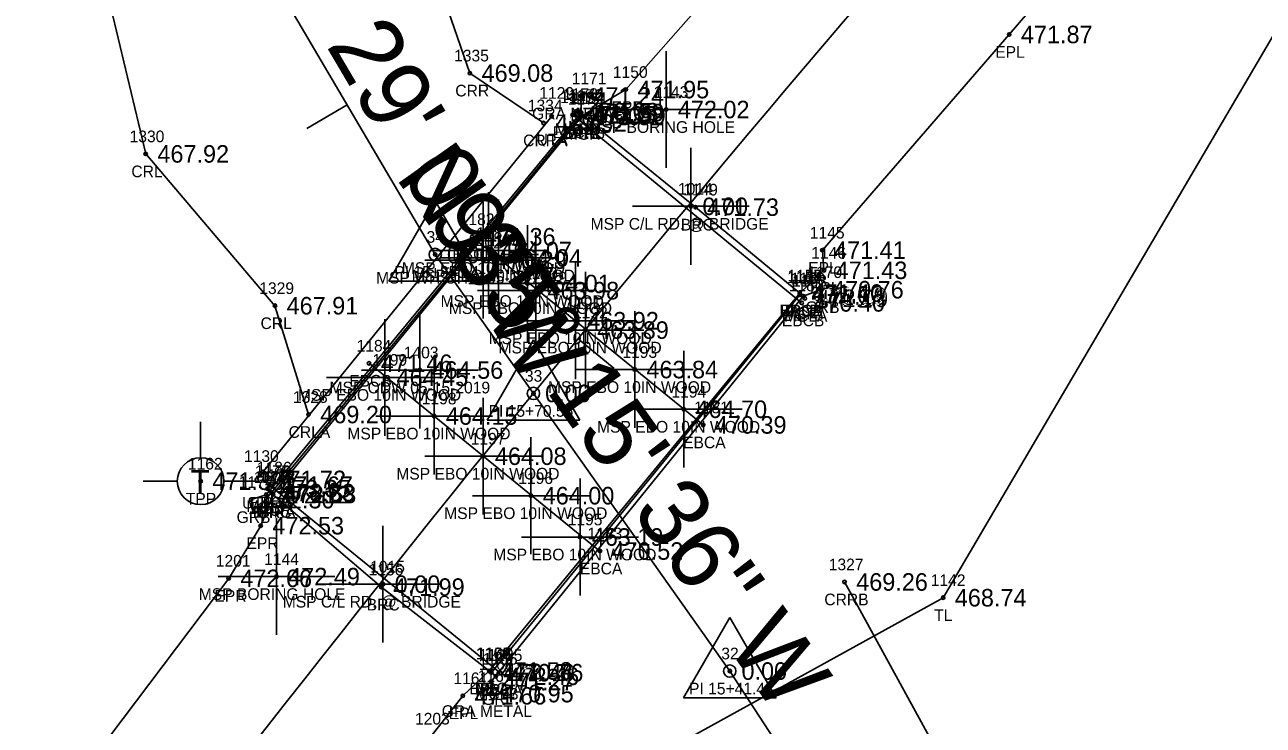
# Model space of a CAD drawing. Extents: x 1740701 to 1743138, y 748181 to 751839.
# Drawn here: x 1741552.9 to 1741658.9, y 750033.3 to 750093.3 of the extents above; entities that cross this region are included whole.
import ezdxf

# ---------------------------------------------------------------- set-up
doc = ezdxf.new("R2010")
doc.units = 0
for name, color, linetype in [('RD_EX_Bridge', 7, 'Continuous'), ('RD_EX_Bridge_txCode', 7, 'Continuous'), ('RD_EX_Conc', 7, 'Continuous'), ('RD_EX_Conc_txCode', 7, 'Continuous'), ('RD_EX_GuardRail', 7, 'Continuous'), ('RD_EX_GuardRail_txCode', 7, 'Continuous'), ('RD_EX_H2O', 7, 'Continuous'), ('RD_EX_H2O_txCode', 7, 'Continuous'), ('RD_EX_Misc', 7, 'Continuous'), ('RD_EX_Misc_txCode', 7, 'Continuous'), ('RD_EX_Road', 7, 'Continuous'), ('RD_EX_Road_txCode', 7, 'Continuous'), ('RD_EX_TX_Bridge_ELEV', 7, 'Continuous'), ('RD_EX_TX_Conc_ELEV', 7, 'Continuous'), ('RD_EX_TX_GuardRail_ELEV', 7, 'Continuous'), ('RD_EX_TX_H2O_ELEV', 7, 'Continuous'), ('RD_EX_TX_Misc_ELEV', 7, 'Continuous'), ('RD_EX_TX_Road_ELEV', 7, 'Continuous'), ('RD_EX_TX_UT_ELEV', 7, 'Continuous'), ('RD_EX_TX_VEG_ELEV', 7, 'Continuous'), ('RD_EX_UT', 7, 'Continuous'), ('RD_EX_UT_txCode', 7, 'Continuous'), ('RD_EX_VEG', 7, 'Continuous'), ('RD_EX_VEG_txCode', 7, 'Continuous'), ('RD_HC_Cl', 7, 'Continuous'), ('RD_HC_Data', 7, 'Continuous'), ('RD_HC_Data_Tic', 7, 'Continuous'), ('RD_HC_Survey_ELEV', 7, 'Continuous'), ('RD_HC_txCode', 7, 'Continuous'), ('RD_SMD_Locator', 7, 'Continuous')]:
    doc.layers.add(name, color=color, linetype=linetype)

msp = doc.modelspace()

# ---------------------------------------------------------------- linework, layer by layer
at = {"layer": 'RD_EX_Bridge'}
for p, q in [((1741599.8, 750085.54), (1741619.4, 750069.43)), ((1741592.6, 750068.91), (1741592.6, 750078.91)), ((1741593.46, 750068.28), (1741593.46, 750078.28)), ((1741595.92, 750066.09), (1741595.92, 750076.09)), ((1741610.97, 750058.98), (1741591.2, 750075.09)), ((1741596.64, 750065.48), (1741596.64, 750075.48)), ((1741587.6, 750073.91), (1741597.6, 750073.91)), ((1741588.46, 750073.28), (1741598.46, 750073.28)), ((1741600.04, 750062.9), (1741600.04, 750072.9)), ((1741600.89, 750062.1), (1741600.89, 750072.1)), ((1741590.92, 750071.09), (1741600.92, 750071.09)), ((1741591.64, 750070.48), (1741601.64, 750070.48)), ((1741605.11, 750058.72), (1741605.11, 750068.72)), ((1741583.72, 750058.05), (1741583.72, 750068.05)), ((1741595.04, 750067.9), (1741605.04, 750067.9)), ((1741595.89, 750067.1), (1741605.89, 750067.1)), ((1741609.31, 750055.32), (1741609.31, 750065.32)), ((1741602.13, 750048.18), (1741582.37, 750064.26)), ((1741587.94, 750054.74), (1741587.94, 750064.74)), ((1741578.72, 750063.05), (1741588.72, 750063.05)), ((1741600.11, 750063.72), (1741610.11, 750063.72)), ((1741592.14, 750051.3), (1741592.14, 750061.3)), ((1741604.31, 750060.32), (1741614.31, 750060.32)), ((1741582.94, 750059.74), (1741592.94, 750059.74)), ((1741596.23, 750047.92), (1741596.23, 750057.92)), ((1741587.14, 750056.3), (1741597.14, 750056.3)), ((1741593.58, 750037.76), (1741573.85, 750053.82)), ((1741600.43, 750044.38), (1741600.43, 750054.38)), ((1741591.23, 750052.92), (1741601.23, 750052.92)), ((1741595.43, 750049.38), (1741605.43, 750049.38))]:
    msp.add_line(p, q, dxfattribs=at)
msp.add_lwpolyline([(1741619.24, 750070.27), (1741610.32, 750077.63), (1741600.63, 750085.47), (1741574.14, 750053.03), (1741583.42, 750045.09), (1741592.65, 750037.91), (1741592.65, 750037.91), (1741619.24, 750070.27)], dxfattribs=at)
for centre in [(1741592.6, 750073.91), (1741593.46, 750073.28), (1741595.92, 750071.09), (1741596.64, 750070.48), (1741600.04, 750067.9), (1741600.89, 750067.1), (1741583.72, 750063.05), (1741605.11, 750063.72), (1741587.94, 750059.74), (1741609.31, 750060.32), (1741592.14, 750056.3), (1741596.23, 750052.92), (1741600.43, 750049.38)]:
    msp.add_circle(centre, 0.15, dxfattribs=at)
at = {"layer": 'RD_EX_Conc'}
for points in [[(1741573.67, 750053.52), (1741574.02, 750053.18), (1741600.44, 750085.4), (1741600.04, 750085.81)], [(1741619.67, 750069.82), (1741619.25, 750070.12), (1741592.84, 750037.78), (1741593.22, 750037.45)]]:
    msp.add_lwpolyline(points, dxfattribs=at)
at = {"layer": 'RD_EX_GuardRail'}
for points in [[(1741600.49, 750087.15), (1741600.52, 750085.73), (1741573.56, 750053), (1741572.28, 750052.58)], [(1741592.75, 750035.97), (1741592.83, 750037), (1741619.54, 750070.01), (1741621, 750070.56)]]:
    msp.add_lwpolyline(points, dxfattribs=at)
at = {"layer": 'RD_EX_H2O'}
for p, q in [((1741592.15, 750068.09), (1741592.15, 750078.09)), ((1741587.15, 750073.09), (1741597.15, 750073.09)), ((1741586.72, 750058.68), (1741586.72, 750068.68)), ((1741581.72, 750063.68), (1741591.72, 750063.68))]:
    msp.add_line(p, q, dxfattribs=at)
for points in [[(1741577.19, 750059.87), (1741574.31, 750069.19), (1741563.25, 750082.19), (1741560.12, 750095.32), (1741559.96, 750109.5), (1741556.5, 750127.16), (1741554.14, 750131.7), (1741543.79, 750140.45), (1741537.22, 750131.72), (1741525.85, 750130.27), (1741518.7, 750134.1), (1741490.89, 750135.06), (1741436.94, 750142.19), (1741375.71, 750163.12), (1741339.37, 750188.79), (1741331.64, 750190.2), (1741328.64, 750186.11), (1741320.24, 750158.32), (1741318.27, 750146.83), (1741309.48, 750135.97), (1741304.66, 750127.91)], [(1741597.3, 750084.84), (1741591, 750089.11), (1741586.21, 750103), (1741580.45, 750128.97), (1741581.18, 750134.22), (1741591.16, 750136.52)], [(1742009.73, 749699.92), (1741998.41, 749723.73), (1741963.19, 749743.52), (1741899.78, 749744.87), (1741875.61, 749759.72), (1741846.8, 749796.06), (1741820.86, 749838.72), (1741812.23, 749854.24), (1741798.02, 749868.34), (1741757.86, 749894.19), (1741733.12, 749942.57), (1741724.29, 749959.1), (1741692.79, 749978.15), (1741670.02, 749986.94), (1741660.12, 749986.72), (1741653.47, 749993.98), (1741643.26, 750008.63), (1741623.07, 750045.53)]]:
    msp.add_lwpolyline(points, dxfattribs=at)
for centre in [(1741592.15, 750073.09), (1741586.72, 750063.68)]:
    msp.add_circle(centre, 0.15, dxfattribs=at)
at = {"layer": 'RD_EX_Misc'}
for p, q in [((1741607.8, 750080.99), (1741607.8, 750090.99)), ((1741602.8, 750085.99), (1741612.8, 750085.99)), ((1741609.91, 750072.7), (1741609.91, 750082.7)), ((1741604.91, 750077.7), (1741614.91, 750077.7)), ((1741574.45, 750040.99), (1741574.45, 750050.99)), ((1741583.56, 750040.34), (1741583.56, 750050.34)), ((1741569.45, 750045.99), (1741579.45, 750045.99)), ((1741578.56, 750045.34), (1741588.56, 750045.34))]:
    msp.add_line(p, q, dxfattribs=at)
at = {"layer": 'RD_EX_Road'}
for points in [[(1742095.24, 750593.27), (1742088.27, 750587.97), (1742078.23, 750580.89), (1742049.13, 750555.21), (1742012.94, 750522.73), (1741975.54, 750488.03), (1741940.71, 750452.82), (1741916.22, 750428.67), (1741904.72, 750416.99), (1741884.38, 750395.02), (1741870.75, 750380.27), (1741817.36, 750322.98), (1741803.89, 750307.66), (1741783.86, 750287.33), (1741735.44, 750234.07), (1741718.84, 750214.98), (1741710.25, 750205.58), (1741668.97, 750159.8), (1741635, 750122.49), (1741604.35, 750087.7), (1741600.63, 750085.47)], [(1742102.43, 750570.61), (1742093.26, 750562.71), (1742064.72, 750538.42), (1742027.92, 750505.65), (1741991.25, 750471.83), (1741956.32, 750436.98), (1741921.43, 750401.39), (1741886.79, 750364.93), (1741819.64, 750292.67), (1741751.78, 750219.01), (1741684.42, 750145.59), (1741650.98, 750108.5), (1741637.17, 750092.42), (1741621.17, 750073.94), (1741621.31, 750072.22), (1741619.24, 750070.27)], [(1741574.14, 750053.03), (1741573.09, 750050.35), (1741570.35, 750045.84), (1741539.87, 750005.43), (1741510.87, 749966.19), (1741482.97, 749924.75), (1741454.76, 749883.01), (1741427.14, 749841.37), (1741399.6, 749799.14), (1741372.83, 749758.13), (1741317.93, 749673.6), (1741267.39, 749595.97), (1741263.6, 749591.05), (1741254, 749576.22), (1741209.28, 749507.22), (1741154.74, 749422.71)], [(1741592.65, 750037.91), (1741590.39, 750035.78), (1741587.68, 750032.32), (1741557.76, 749993.29), (1741528.74, 749952.66), (1741501.16, 749912.21), (1741473.5, 749870.53), (1741446.05, 749829.26), (1741418.1, 749787.13), (1741391.18, 749745.79), (1741336.54, 749661.65), (1741282.05, 749578.36), (1741227.71, 749494.6), (1741173.28, 749411)]]:
    msp.add_lwpolyline(points, dxfattribs=at)
at = {"layer": 'RD_EX_UT'}
for p, q in [((1741598, 750085.41), (1741572.76, 750054.31)), ((1741567.95, 750059.23), (1741567.95, 750056.16)), ((1741563.02, 750054.17), (1741565.95, 750054.17)), ((1741569.95, 750054.17), (1741573.02, 750054.17))]:
    msp.add_line(p, q, dxfattribs=at)
msp.add_circle((1741567.95, 750054.16), 2, dxfattribs=at)
at = {"layer": 'RD_EX_VEG'}
msp.add_lwpolyline([(1742114.37, 750556.95), (1742102.57, 750548.5), (1742074.74, 750526.88), (1742042.48, 750492.43), (1742005.49, 750457.25), (1741971.49, 750420.27), (1741936.96, 750386.65), (1741902.94, 750350.76), (1741835.15, 750278.46), (1741766.69, 750206.43), (1741693.82, 750135.64), (1741661.95, 750096.11), (1741631.51, 750044.18), (1741602.3, 750028.04), (1741573.25, 749982.32), (1741544.84, 749941.06), (1741514.68, 749901.47), (1741495.89, 749858.02), (1741462.75, 749819.18), (1741434.73, 749775.9), (1741408.39, 749735.06), (1741355.53, 749651.67)], dxfattribs=at)
at = {"layer": 'RD_HC_Cl'}
for p, q in [((1741588.03, 750073.58), (1741574.57, 750096.44)), ((1741613.25, 750037.9), (1741588.03, 750073.58)), ((1741655.6, 749972.85), (1741613.25, 750037.9))]:
    msp.add_line(p, q, dxfattribs=at)
msp.add_arc((1743076.32, 748855.91), 1908.9, 137.32219, 146.96645, dxfattribs=at)
at = {"layer": 'RD_HC_Data'}
for p, q in [((1741584.05, 750071.29), (1741588.03, 750078.17)), ((1741588.03, 750078.17), (1741592, 750071.29)), ((1741584.05, 750071.29), (1741592, 750071.29)), ((1741592.47, 750059.39), (1741596.44, 750066.26)), ((1741596.44, 750066.26), (1741600.41, 750059.39)), ((1741592.47, 750059.39), (1741600.41, 750059.39)), ((1741609.28, 750035.6), (1741613.26, 750042.48)), ((1741613.26, 750042.48), (1741617.22, 750035.6)), ((1741609.28, 750035.6), (1741617.22, 750035.6))]:
    msp.add_line(p, q, dxfattribs=at)
for centre in [(1741588.03, 750073.58), (1741596.44, 750061.68), (1741613.25, 750037.9)]:
    msp.add_circle(centre, 0.529, dxfattribs=at)
at = {"layer": 'RD_HC_Data_Tic'}
for p, q in [((1741580.49, 750086.39), (1741577.04, 750084.36)), ((1741600.27, 750066.36), (1741603.36, 750063.82))]:
    msp.add_line(p, q, dxfattribs=at)
at = {"layer": 'RD_SMD_Locator'}
for centre in [(1741637.17, 750092.42), (1741591, 750089.11), (1741604.35, 750087.7), (1741600.49, 750087.15), (1741598, 750085.41), (1741599.8, 750085.54), (1741600.04, 750085.81), (1741600.44, 750085.4), (1741600.52, 750085.73), (1741600.63, 750085.47), (1741600.63, 750085.47), (1741607.8, 750085.99), (1741597.3, 750084.84), (1741563.25, 750082.19), (1741609.91, 750077.7), (1741610.32, 750077.63), (1741591.2, 750075.09), (1741588.03, 750073.58), (1741621.17, 750073.94), (1741621.31, 750072.22), (1741619.24, 750070.27), (1741619.24, 750070.27), (1741619.24, 750070.27), (1741621, 750070.56), (1741574.31, 750069.19), (1741619.25, 750070.12), (1741619.4, 750069.43), (1741619.54, 750070.01), (1741619.67, 750069.82), (1741582.37, 750064.26), (1741596.44, 750061.68), (1741577.19, 750059.87), (1741610.97, 750058.98), (1741567.95, 750054.16), (1741572.76, 750054.31), (1741573.67, 750053.52), (1741573.85, 750053.82), (1741572.28, 750052.58), (1741573.56, 750053), (1741574.02, 750053.18), (1741574.14, 750053.03), (1741574.14, 750053.03), (1741573.09, 750050.35), (1741602.13, 750048.18), (1741574.45, 750045.99), (1741570.35, 750045.84), (1741583.42, 750045.09), (1741583.56, 750045.34), (1741623.07, 750045.53), (1741631.51, 750044.18), (1741592.65, 750037.91), (1741592.65, 750037.91), (1741592.65, 750037.91), (1741592.84, 750037.78), (1741593.22, 750037.45), (1741593.58, 750037.76), (1741613.25, 750037.9), (1741592.83, 750037), (1741590.39, 750035.78), (1741592.75, 750035.97)]:
    msp.add_circle(centre, 0.15, dxfattribs=at)

# ---------------------------------------------------------------- texts
at = {"layer": 'RD_EX_Bridge_txCode'}
for s, p in [('1179', (1741598.73, 750086.54)), ('1152', (1741599.57, 750086.47)), ('EBCA', (1741598.08, 750083.54)), ('BRC', (1741599.38, 750083.47)), ('1149', (1741609.25, 750078.63)), ('1182', (1741590.13, 750076.09)), ('1187', (1741591.54, 750074.91)), ('BRC', (1741609.06, 750075.63)), ('1188', (1741592.4, 750074.28)), ('EBCB', (1741589.49, 750073.09)), ('MSP EBO 10IN WOOD', (1741585.17, 750071.91)), ('1189', (1741594.86, 750072.09)), ('MSP EBO 10IN WOOD', (1741586.03, 750071.28)), ('1190', (1741595.54, 750071.48)), ('1148', (1741618.18, 750071.27)), ('1159', (1741618.18, 750071.27)), ('1180', (1741618.3, 750070.43)), ('MSP EBO 10IN WOOD', (1741588.49, 750069.09)), ('MSP EBO 10IN WOOD', (1741589.2, 750068.48)), ('1191', (1741599.26, 750068.9)), ('1192', (1741599.82, 750068.1)), ('BRCA', (1741617.5, 750068.27)), ('BRCB', (1741617.52, 750068.27)), ('EBCB', (1741617.7, 750067.43)), ('1184', (1741581.3, 750065.26)), ('MSP EBO 10IN WOOD', (1741592.6, 750065.9)), ('MSP EBO 10IN WOOD', (1741593.45, 750065.1)), ('1193', (1741604.05, 750064.72)), ('1199', (1741582.65, 750064.05)), ('EBCB', (1741580.67, 750062.26)), ('MSP EBO 10IN WOOD', (1741576.28, 750061.05)), ('MSP EBO 10IN WOOD', (1741597.68, 750061.72)), ('1194', (1741608.25, 750061.32)), ('1198', (1741586.88, 750060.74)), ('1181', (1741610.19, 750059.98)), ('MSP EBO 10IN WOOD', (1741580.51, 750057.74)), ('MSP EBO 10IN WOOD', (1741601.88, 750058.32)), ('1197', (1741591.07, 750057.3)), ('EBCA', (1741609.25, 750056.98)), ('1186', (1741572.76, 750054.82)), ('1153', (1741573.08, 750054.03)), ('MSP EBO 10IN WOOD', (1741584.7, 750054.3)), ('1196', (1741595.14, 750053.92)), ('EBCB', (1741572.15, 750051.82)), ('BRC', (1741572.89, 750051.03)), ('MSP EBO 10IN WOOD', (1741588.8, 750050.92)), ('1195', (1741599.37, 750050.38)), ('1183', (1741601.06, 750049.18)), ('MSP EBO 10IN WOOD', (1741593, 750047.38)), ('1156', (1741582.33, 750046.09)), ('EBCA', (1741600.41, 750046.18)), ('BRC', (1741582.17, 750043.09)), ('1158', (1741591.58, 750038.91)), ('1157', (1741591.58, 750038.91)), ('1185', (1741592.52, 750038.76)), ('BRC', (1741591.4, 750035.91)), ('BRC', (1741591.4, 750035.91)), ('EBCA', (1741591.87, 750035.76))]:
    msp.add_text(s, height=1, dxfattribs=at).set_placement(p)
at = {"layer": 'RD_EX_Conc_txCode'}
for s, p in [('1178', (1741598.98, 750086.81)), ('1177', (1741599.38, 750086.4)), ('MCRB', (1741598.25, 750083.81)), ('MCR', (1741599.13, 750083.4)), ('1164', (1741618.16, 750071.12)), ('1163', (1741618.59, 750070.82)), ('MCLA', (1741617.89, 750067.82)), ('MCL', (1741617.96, 750068.12)), ('1175', (1741572.6, 750054.52)), ('1176', (1741572.93, 750054.18)), ('MCRA', (1741571.86, 750051.52)), ('MCR', (1741572.7, 750051.18)), ('1165', (1741591.75, 750038.78)), ('1166', (1741592.11, 750038.45)), ('MCL', (1741591.54, 750035.78)), ('MCLB', (1741591.46, 750035.45))]:
    msp.add_text(s, height=1, dxfattribs=at).set_placement(p)
at = {"layer": 'RD_EX_GuardRail_txCode'}
for s, p in [('1171', (1741599.71, 750088.15)), ('1172', (1741599.46, 750086.73)), ('GRA METAL', (1741596.33, 750085.15)), ('GR', (1741599.74, 750083.73)), ('1170', (1741619.89, 750071.56)), ('1169', (1741618.45, 750071.01)), ('GRB', (1741619.74, 750068.56)), ('GR', (1741618.76, 750068.01)), ('1174', (1741571.22, 750053.58)), ('1173', (1741572.5, 750054)), ('GRB', (1741571.03, 750050.58)), ('GR', (1741572.78, 750051)), ('1168', (1741591.75, 750038)), ('1167', (1741591.67, 750036.97)), ('GR', (1741592.05, 750035)), ('GRA METAL', (1741588.59, 750033.97))]:
    msp.add_text(s, height=1, dxfattribs=at).set_placement(p)
at = {"layer": 'RD_EX_H2O_txCode'}
for s, p in [('1335', (1741589.65, 750090.11)), ('CRR', (1741589.75, 750087.11)), ('1334', (1741595.96, 750085.84)), ('1330', (1741561.87, 750083.19)), ('CRRA', (1741595.56, 750082.84)), ('CRL', (1741562.02, 750080.19)), ('1402', (1741590.76, 750074.09)), ('MSP WH OHW 05-16-2019', (1741582.97, 750071.09)), ('1329', (1741572.97, 750070.19)), ('CRL', (1741573.08, 750067.19)), ('1403', (1741585.34, 750064.68)), ('MSP ODW 05-15-2019', (1741578.98, 750061.68)), ('1328', (1741575.85, 750060.87)), ('CRLA', (1741575.48, 750057.87)), ('1327', (1741621.72, 750046.53)), ('CRRB', (1741621.34, 750043.53))]:
    msp.add_text(s, height=1, dxfattribs=at).set_placement(p)
at = {"layer": 'RD_EX_Misc_txCode'}
for s, p in [('1143', (1741606.73, 750086.99)), ('MSP BORING HOLE', (1741601.14, 750083.99)), ('1014', (1741608.81, 750078.7)), ('MSP C/L RD. @ BRIDGE', (1741601.33, 750075.7)), ('1144', (1741573.39, 750046.99)), ('1015', (1741582.46, 750046.34)), ('MSP BORING HOLE', (1741567.79, 750043.99)), ('MSP C/L RD. @ BRIDGE', (1741574.98, 750043.34))]:
    msp.add_text(s, height=1, dxfattribs=at).set_placement(p)
at = {"layer": 'RD_EX_Road_txCode'}
for s, p in [('EPL', (1741635.97, 750090.42)), ('1150', (1741603.24, 750088.7)), ('1151', (1741599.85, 750086.47)), ('EPR', (1741603.12, 750085.7)), ('EPRB', (1741598.93, 750083.47)), ('1145', (1741620.1, 750074.94)), ('1146', (1741620.22, 750073.22)), ('EPL', (1741619.96, 750071.94)), ('1147', (1741618.18, 750071.27)), ('EPL', (1741620.11, 750070.22)), ('EPLB', (1741617.56, 750068.27)), ('1154', (1741573.08, 750054.03)), ('1155', (1741572.03, 750051.35)), ('EPRA', (1741572.42, 750051.03)), ('EPR', (1741571.87, 750048.35)), ('1201', (1741569.25, 750046.84)), ('EPR', (1741569.13, 750043.84)), ('1160', (1741591.52, 750038.91)), ('1161', (1741589.59, 750036.78)), ('EPLA', (1741590.95, 750035.91)), ('EPL', (1741589.19, 750033.78)), ('1203', (1741586.3, 750033.32))]:
    msp.add_text(s, height=1, dxfattribs=at).set_placement(p)
at = {"layer": 'RD_EX_TX_Bridge_ELEV'}
for s, p in [('471.35', (1741600.8, 750084.79)), ('471.99', (1741601.63, 750084.72)), ('471.73', (1741611.32, 750076.88)), ('471.36', (1741592.2, 750074.34)), ('464.07', (1741593.6, 750073.16)), ('464.04', (1741594.46, 750072.53)), ('464.01', (1741596.92, 750070.34)), ('463.98', (1741597.64, 750069.73)), ('471.40', (1741620.24, 750069.52)), ('471.40', (1741620.24, 750069.52)), ('470.40', (1741620.4, 750068.68)), ('463.92', (1741601.04, 750067.15)), ('463.89', (1741601.89, 750066.35)), ('471.46', (1741583.37, 750063.51)), ('463.84', (1741606.11, 750062.97)), ('464.45', (1741584.72, 750062.3)), ('464.70', (1741610.31, 750059.57)), ('464.15', (1741588.94, 750058.99)), ('470.39', (1741611.97, 750058.23)), ('464.08', (1741593.14, 750055.55)), ('471.67', (1741574.85, 750053.07)), ('472.53', (1741575.14, 750052.28)), ('464.00', (1741597.23, 750052.17)), ('463.19', (1741601.43, 750048.63)), ('470.52', (1741603.13, 750047.43)), ('471.99', (1741584.42, 750044.34)), ('471.58', (1741593.65, 750037.16)), ('471.58', (1741593.65, 750037.16)), ('470.76', (1741594.58, 750037.01))]:
    msp.add_text(s, height=1.5, dxfattribs=at).set_placement(p)
at = {"layer": 'RD_EX_TX_Conc_ELEV'}
for s, p in [('473.03', (1741601.04, 750085.06)), ('473.02', (1741601.44, 750084.65)), ('472.09', (1741620.25, 750069.37)), ('472.09', (1741620.67, 750069.07)), ('473.35', (1741574.67, 750052.77)), ('473.33', (1741575.02, 750052.43)), ('472.40', (1741593.84, 750037.03)), ('472.46', (1741594.22, 750036.7))]:
    msp.add_text(s, height=1.5, dxfattribs=at).set_placement(p)
at = {"layer": 'RD_EX_TX_GuardRail_ELEV'}
for s, p in [('471.24', (1741601.49, 750086.4)), ('471.59', (1741601.52, 750084.98)), ('471.19', (1741620.54, 750069.26)), ('470.76', (1741622, 750069.81)), ('472.12', (1741574.56, 750052.25)), ('472.30', (1741573.28, 750051.83)), ('471.27', (1741593.83, 750036.25)), ('470.95', (1741593.75, 750035.22))]:
    msp.add_text(s, height=1.5, dxfattribs=at).set_placement(p)
at = {"layer": 'RD_EX_TX_H2O_ELEV'}
for s, p in [('469.08', (1741592, 750088.36)), ('469.92', (1741598.3, 750084.09)), ('467.92', (1741564.25, 750081.44)), ('470.29', (1741593.15, 750072.34)), ('467.91', (1741575.31, 750068.44)), ('464.56', (1741587.72, 750062.93)), ('469.20', (1741578.19, 750059.12)), ('469.26', (1741624.07, 750044.78))]:
    msp.add_text(s, height=1.5, dxfattribs=at).set_placement(p)
at = {"layer": 'RD_EX_TX_Misc_ELEV'}
for s, p in [('472.02', (1741608.8, 750085.24)), ('0.00', (1741610.91, 750076.95)), ('472.49', (1741575.45, 750045.24)), ('0.00', (1741584.56, 750044.59))]:
    msp.add_text(s, height=1.5, dxfattribs=at).set_placement(p)
at = {"layer": 'RD_EX_TX_Road_ELEV'}
for s, p in [('471.87', (1741638.17, 750091.67)), ('471.95', (1741605.35, 750086.95)), ('471.99', (1741601.63, 750084.72)), ('471.41', (1741622.17, 750073.19)), ('471.43', (1741622.31, 750071.47)), ('471.40', (1741620.24, 750069.52)), ('472.53', (1741575.14, 750052.28)), ('472.53', (1741574.09, 750049.6)), ('472.66', (1741571.35, 750045.09)), ('471.58', (1741593.65, 750037.16)), ('471.66', (1741591.39, 750035.03))]:
    msp.add_text(s, height=1.5, dxfattribs=at).set_placement(p)
at = {"layer": 'RD_EX_TX_UT_ELEV'}
for s, p in [('470.70', (1741599.5, 750084.66)), ('471.38', (1741568.95, 750053.41)), ('471.72', (1741574.26, 750053.56))]:
    msp.add_text(s, height=1.5, dxfattribs=at).set_placement(p)
at = {"layer": 'RD_EX_TX_VEG_ELEV'}
msp.add_text('468.74', height=1.5, dxfattribs=at).set_placement((1741632.51, 750043.43))
at = {"layer": 'RD_EX_UT'}
msp.add_text('T', height=2, dxfattribs=at).set_placement((1741567.1, 750053.11))
at = {"layer": 'RD_EX_UT_txCode'}
for s, p in [('1129', (1741596.94, 750086.91)), ('UTA', (1741596.71, 750082.91)), ('1130', (1741571.66, 750055.81)), ('1162', (1741566.86, 750055.16)), ('TPP', (1741566.68, 750052.16)), ('UTB', (1741571.49, 750051.81))]:
    msp.add_text(s, height=1, dxfattribs=at).set_placement(p)
at = {"layer": 'RD_EX_VEG_txCode'}
for s, p in [('1142', (1741630.45, 750045.18)), ('TL', (1741630.74, 750042.18))]:
    msp.add_text(s, height=1, dxfattribs=at).set_placement(p)
at = {"layer": 'RD_HC_Data'}
for s, rotation, p in [('N 30%%d 29\' 09" W', 300.4857, (1741567.28, 750110.79)), ('N 35%%d 15\' 36" W', 305.26, (1741584.53, 750080.26))]:
    msp.add_text(s, height=6, rotation=rotation, dxfattribs=at).set_placement(p)
at = {"layer": 'RD_HC_Survey_ELEV'}
for p in [(1741589.03, 750072.83), (1741597.44, 750060.93), (1741614.25, 750037.15)]:
    msp.add_text('0.00', height=1.5, dxfattribs=at).set_placement(p)
at = {"layer": 'RD_HC_txCode'}
for s, p in [('34', (1741587.29, 750074.58)), ('PI 15+85.14', (1741584.53, 750071.58)), ('33', (1741595.71, 750062.68)), ('PI 15+70.56', (1741592.6, 750059.68)), ('32', (1741612.52, 750038.9)), ('PI 15+41.44', (1741609.76, 750035.9))]:
    msp.add_text(s, height=1, dxfattribs=at).set_placement(p)

doc.saveas('drawing.dxf')
